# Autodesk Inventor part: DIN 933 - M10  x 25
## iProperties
Comments: To add or edit properties for Autodesk Inventor files, use iProperties.
Created: 2003-09
Part Number: DIN 933 - M10  x 25
Vendor: Autodesk Inc.
Document SubType Name: Modeling
Designer: lamberj
Material: Default
Description: Hex-Head Bolt
Standard: DIN 933
Manufacturer: Standard
Standards Organization: Custom
Alert: To add or edit properties for Autodesk Inventor files, use iProperties.
Control State: 0
Master: False
Checked Out: False
Shininess: 64.0
Length Units: 11269
Angle Units: 11279
Time Units: 11290
Mass Units: 11283
Length Display Precision: 3
Angle Display Precision: 2
Compacted: True
EGR: 1
Classification: un/spsc 31161513
Density: 0.0
Volumn: 0.0
Area: 0.0
PropertySet Name: Model Information
Author: lamberj
Revision Number: 5
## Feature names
1. Body [Revolution]
2. Head [Extrusion]
3. Chamfer1 [Revolution]
4. Chamfer2
